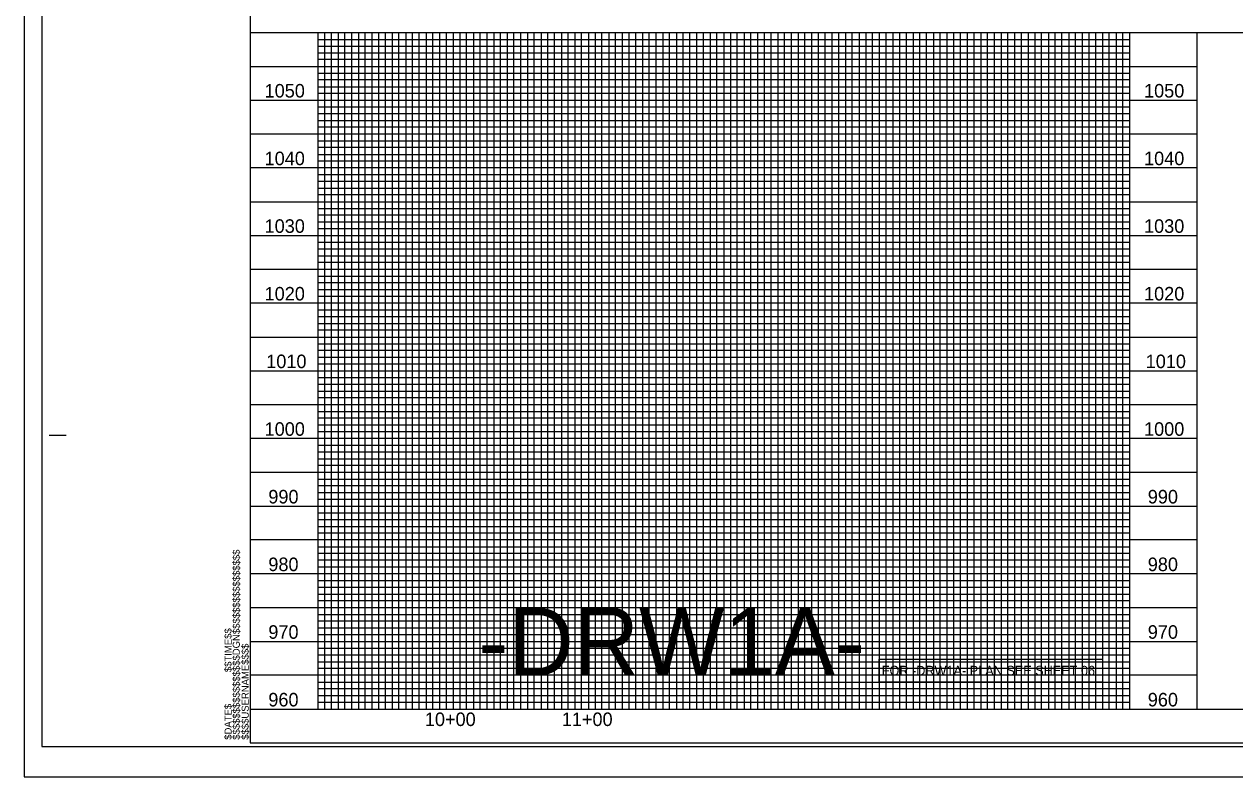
# Model space of a CAD drawing. Extents: x 1260439 to 1262228, y 742196 to 743296.
# Drawn here: x 1260439 to 1261333, y 742196 to 742752 of the extents above; entities that cross this region are included whole.
import ezdxf

# ---------------------------------------------------------------- set-up
doc = ezdxf.new("R2010")
doc.units = 0
for name, color, linetype in [('Exist Vertical Profile Horizontal Axis Label Major', 7, 'Continuous'), ('Exist Vertical Profile Vertical Axis Label', 7, 'Continuous'), ('Prop Grid Mask', 7, 'Continuous'), ('Prop PFL Text', 7, 'Continuous'), ('Sheet Block System Information CELL', 7, 'Continuous'), ('Sheet Cutting Line CELL', 7, 'Continuous'), ('Sheet Data Field CELL', 7, 'Continuous'), ('Sheet Plot Border Inside CELL', 7, 'Continuous'), ('Sheet Plot Border Outside CELL', 7, 'Continuous'), ('Sheet Profile CELL', 7, 'Continuous'), ('Sheet Profile Grid Major CELL', 7, 'Continuous'), ('Sheet Profile Grid Middle CELL', 7, 'Continuous'), ('Sheet Profile Grid Minor CELL', 7, 'Continuous')]:
    doc.layers.add(name, color=color, linetype=linetype)

msp = doc.modelspace()

# ---------------------------------------------------------------- linework, layer by layer
at = {"layer": 'Prop Grid Mask'}
msp.add_lwpolyline([(1261070.75, 742282.74), (1261235.75, 742282.74), (1261235.75, 742265.74), (1261070.75, 742265.74)], close=True, dxfattribs=at)
at = {"layer": 'Sheet Block System Information CELL'}
msp.add_line((1260605.75, 742220.74), (1260605.75, 742220.74), dxfattribs=at)
at = {"layer": 'Sheet Cutting Line CELL'}
msp.add_line((1260438.75, 743295.74), (1260438.75, 742195.74), dxfattribs=at)
at = {"layer": 'Sheet Plot Border Inside CELL'}
msp.add_lwpolyline([(1260451.75, 742218.19), (1262118.25, 742218.19), (1262118.25, 743273.29), (1260451.75, 743273.29)], close=True, dxfattribs=at)
at = {"layer": 'Sheet Plot Border Outside CELL'}
msp.add_lwpolyline([(1260438.75, 742195.74), (1262122.75, 742195.74), (1262122.75, 743295.74), (1260438.75, 743295.74)], close=True, dxfattribs=at)
at = {"layer": 'Sheet Profile CELL'}
for p, q in [((1260605.75, 742745.74), (1262105.75, 742745.74)), ((1260457.25, 742448.24), (1260469.75, 742448.24)), ((1260605.75, 742245.74), (1262105.75, 742245.74))]:
    msp.add_line(p, q, dxfattribs=at)
msp.add_lwpolyline([(1262105.75, 743270.74), (1260605.75, 743270.74), (1260605.75, 742220.74), (1262105.75, 742220.74)], close=True, dxfattribs=at)
at = {"layer": 'Sheet Profile Grid Major CELL'}
for p, q in [((1260655.75, 742745.74), (1260655.75, 742245.74)), ((1260705.75, 742245.74), (1260705.75, 742745.74)), ((1260705.75, 742745.74), (1260755.75, 742745.74)), ((1260755.75, 742745.74), (1260755.75, 742245.74)), ((1260805.75, 742245.74), (1260805.75, 742745.74)), ((1260805.75, 742745.74), (1260855.75, 742745.74)), ((1260855.75, 742745.74), (1260855.75, 742245.74)), ((1260905.75, 742245.74), (1260905.75, 742745.74)), ((1260905.75, 742745.74), (1260955.75, 742745.74)), ((1260955.75, 742745.74), (1260955.75, 742245.74)), ((1261005.75, 742245.74), (1261005.75, 742745.74)), ((1261005.75, 742745.74), (1261055.75, 742745.74)), ((1261055.75, 742745.74), (1261055.75, 742245.74)), ((1261105.75, 742745.74), (1261155.75, 742745.74)), ((1261105.75, 742245.74), (1261105.75, 742745.74)), ((1261105.75, 742745.74), (1261155.75, 742745.74)), ((1261155.75, 742745.74), (1261155.75, 742245.74)), ((1261205.75, 742745.74), (1261255.75, 742745.74)), ((1261205.75, 742245.74), (1261205.75, 742745.74)), ((1261255.75, 742745.74), (1261255.75, 742245.74)), ((1261305.75, 742745.74), (1261355.75, 742745.74)), ((1261305.75, 742245.74), (1261305.75, 742745.74)), ((1260605.75, 742245.74), (1260605.75, 742245.74)), ((1260655.75, 742245.74), (1260705.75, 742245.74)), ((1260755.75, 742245.74), (1260805.75, 742245.74)), ((1260855.75, 742245.74), (1260905.75, 742245.74)), ((1260955.75, 742245.74), (1261005.75, 742245.74)), ((1261055.75, 742245.74), (1261105.75, 742245.74)), ((1261155.75, 742245.74), (1261205.75, 742245.74)), ((1261255.75, 742245.74), (1261305.75, 742245.74))]:
    msp.add_line(p, q, dxfattribs=at)
for points in [[(1260605.75, 742695.74), (1261305.75, 742695.74)], [(1261305.75, 742645.74), (1260605.75, 742645.74), (1260605.75, 742595.74), (1261305.75, 742595.74)], [(1261305.75, 742545.74), (1260605.75, 742545.74), (1260605.75, 742495.74), (1261305.75, 742495.74)], [(1261305.75, 742445.74), (1260605.75, 742445.74), (1260605.75, 742395.74), (1261305.75, 742395.74)], [(1261305.75, 742345.74), (1260605.75, 742345.74), (1260605.75, 742345.74), (1260605.75, 742295.74), (1261305.75, 742295.74)]]:
    msp.add_lwpolyline(points, dxfattribs=at)
at = {"layer": 'Sheet Profile Grid Middle CELL'}
for p, q in [((1260680.75, 742745.74), (1260680.75, 742245.74)), ((1260730.75, 742245.74), (1260730.75, 742745.74)), ((1260730.75, 742745.74), (1260780.75, 742745.74)), ((1260780.75, 742745.74), (1260780.75, 742245.74)), ((1260830.75, 742245.74), (1260830.75, 742745.74)), ((1260830.75, 742745.74), (1260880.75, 742745.74)), ((1260880.75, 742745.74), (1260880.75, 742245.74)), ((1260930.75, 742245.74), (1260930.75, 742745.74)), ((1260930.75, 742745.74), (1260980.75, 742745.74)), ((1260980.75, 742745.74), (1260980.75, 742245.74)), ((1261030.75, 742245.74), (1261030.75, 742745.74)), ((1261030.75, 742745.74), (1261080.75, 742745.74)), ((1261080.75, 742745.74), (1261080.75, 742245.74)), ((1261130.75, 742245.74), (1261130.75, 742745.74)), ((1261180.75, 742745.74), (1261180.75, 742245.74)), ((1261230.75, 742245.74), (1261230.75, 742745.74)), ((1260605.75, 742720.74), (1261305.75, 742720.74)), ((1260680.75, 742245.74), (1260730.75, 742245.74)), ((1260780.75, 742245.74), (1260830.75, 742245.74)), ((1260880.75, 742245.74), (1260930.75, 742245.74)), ((1260980.75, 742245.74), (1261030.75, 742245.74)), ((1261080.75, 742245.74), (1261130.75, 742245.74)), ((1261230.75, 742245.74), (1261230.75, 742245.74))]:
    msp.add_line(p, q, dxfattribs=at)
for points in [[(1261305.75, 742670.74), (1260605.75, 742670.74), (1260605.75, 742620.74), (1261305.75, 742620.74)], [(1261305.75, 742570.74), (1260605.75, 742570.74), (1260605.75, 742520.74), (1261305.75, 742520.74)], [(1261305.75, 742470.74), (1260605.75, 742470.74), (1260605.75, 742420.74), (1261305.75, 742420.74)], [(1261305.75, 742370.74), (1260605.75, 742370.74), (1260605.75, 742320.74), (1261305.75, 742320.74)], [(1261305.75, 742270.74), (1260605.75, 742270.74)]]:
    msp.add_lwpolyline(points, dxfattribs=at)
at = {"layer": 'Sheet Profile Grid Minor CELL'}
for p, q in [((1260655.75, 742740.74), (1261255.75, 742740.74)), ((1260655.75, 742735.74), (1260655.75, 742735.74)), ((1261255.75, 742735.56), (1260655.75, 742735.39)), ((1260655.75, 742730.74), (1261255.75, 742730.74)), ((1261255.75, 742610.74), (1260655.75, 742610.74)), ((1261255.75, 742605.74), (1260655.75, 742605.74)), ((1261255.75, 742600.74), (1260655.75, 742600.74)), ((1260655.75, 742590.74), (1261255.75, 742590.74)), ((1261255.75, 742585.74), (1260655.75, 742585.74)), ((1260655.75, 742580.74), (1261255.75, 742580.74)), ((1261255.75, 742560.74), (1260655.75, 742560.74)), ((1260655.75, 742555.74), (1261255.75, 742555.74)), ((1261255.75, 742535.74), (1260655.75, 742535.74)), ((1260655.75, 742530.74), (1261255.75, 742530.74)), ((1261255.75, 742510.74), (1260655.75, 742510.74)), ((1260655.75, 742505.74), (1261255.75, 742505.74)), ((1261255.75, 742500.74), (1260655.75, 742500.74)), ((1260655.75, 742490.74), (1261255.75, 742490.74)), ((1261255.75, 742485.74), (1260655.75, 742485.74)), ((1260655.75, 742480.74), (1261255.75, 742480.74)), ((1261255.75, 742475.74), (1260655.75, 742475.74)), ((1260655.75, 742465.74), (1261255.75, 742465.74)), ((1261255.75, 742460.74), (1260655.75, 742460.74)), ((1260655.75, 742455.74), (1261255.75, 742455.74)), ((1261255.75, 742450.74), (1260655.75, 742450.74)), ((1260655.75, 742440.74), (1261255.75, 742440.74)), ((1261255.75, 742435.74), (1260655.75, 742435.74)), ((1260655.75, 742430.74), (1261255.75, 742430.74)), ((1261255.75, 742425.74), (1260655.75, 742425.74)), ((1260655.75, 742415.74), (1261255.75, 742415.74)), ((1261255.75, 742410.74), (1260655.75, 742410.74)), ((1260655.75, 742405.74), (1261255.75, 742405.74)), ((1261255.75, 742400.74), (1260655.75, 742400.74)), ((1260655.75, 742390.74), (1261255.75, 742390.74)), ((1261255.75, 742385.74), (1260655.75, 742385.74)), ((1260655.75, 742380.74), (1261255.75, 742380.74)), ((1261255.75, 742375.74), (1260655.75, 742375.74)), ((1260655.75, 742365.74), (1261255.75, 742365.74)), ((1261255.75, 742360.74), (1260655.75, 742360.74)), ((1261255.75, 742355.74), (1260655.75, 742355.74)), ((1261255.75, 742350.74), (1260655.75, 742350.74)), ((1260655.75, 742340.74), (1261255.75, 742340.74)), ((1261255.75, 742335.74), (1260655.75, 742335.74)), ((1260655.75, 742330.74), (1261255.75, 742330.74)), ((1261255.75, 742325.74), (1260655.75, 742325.74)), ((1260655.75, 742315.74), (1261255.75, 742315.74)), ((1261255.75, 742310.74), (1260655.75, 742310.74)), ((1260655.75, 742305.74), (1261255.75, 742305.74)), ((1261255.75, 742300.74), (1260655.75, 742300.74)), ((1260655.75, 742290.74), (1261255.75, 742290.74)), ((1261255.75, 742285.74), (1260655.75, 742285.74)), ((1260655.75, 742280.74), (1261255.75, 742280.74)), ((1261255.75, 742275.74), (1260655.75, 742275.74)), ((1260655.75, 742265.74), (1261255.75, 742265.74)), ((1261255.75, 742260.74), (1260655.75, 742260.74)), ((1260655.75, 742255.74), (1261255.75, 742255.74))]:
    msp.add_line(p, q, dxfattribs=at)
for points in [[(1260660.75, 742745.74), (1260660.75, 742245.74), (1260665.75, 742245.74), (1260665.75, 742745.74), (1260670.75, 742745.74), (1260670.75, 742245.74), (1260675.75, 742245.74), (1260675.75, 742745.74), (1260685.75, 742745.74), (1260685.75, 742245.74), (1260690.75, 742245.74), (1260690.75, 742745.74), (1260695.75, 742745.74), (1260695.75, 742245.74), (1260700.75, 742245.74), (1260710.75, 742245.74), (1260715.75, 742245.74), (1260715.75, 742745.74), (1260720.75, 742745.74), (1260720.75, 742245.74), (1260725.75, 742245.74), (1260725.75, 742745.74), (1260735.75, 742745.74), (1260735.75, 742245.74), (1260740.75, 742245.74), (1260740.75, 742745.74), (1260745.75, 742745.74), (1260745.75, 742245.74), (1260750.75, 742245.74), (1260750.75, 742745.74), (1260760.75, 742745.74), (1260760.75, 742245.74), (1260765.75, 742245.74), (1260765.75, 742745.74), (1260770.75, 742745.74), (1260770.75, 742245.74), (1260775.75, 742245.74), (1260775.75, 742745.74), (1260785.75, 742745.74), (1260785.75, 742245.74), (1260790.75, 742245.74), (1260790.75, 742745.74), (1260795.75, 742745.74), (1260795.75, 742245.74), (1260800.75, 742245.74), (1260800.75, 742745.74), (1260810.75, 742745.74), (1260810.75, 742245.74), (1260815.75, 742245.74), (1260815.75, 742745.74), (1260820.75, 742745.74), (1260820.75, 742245.74), (1260825.75, 742245.74), (1260825.75, 742745.74), (1260835.75, 742745.74), (1260835.75, 742245.74), (1260840.75, 742245.74), (1260840.75, 742745.74), (1260845.75, 742745.74), (1260845.75, 742245.74), (1260850.75, 742245.74), (1260850.75, 742745.74), (1260860.75, 742745.74), (1260860.75, 742245.74), (1260865.75, 742245.74), (1260865.75, 742745.74), (1260870.75, 742745.74), (1260870.75, 742245.74)], [(1260700.75, 742245.74), (1260700.75, 742745.74), (1260710.75, 742745.74), (1260710.75, 742245.74)], [(1260870.75, 742245.74), (1260875.75, 742245.74), (1260875.75, 742745.74), (1260885.75, 742745.74), (1260885.75, 742245.74), (1260890.75, 742245.74), (1260890.75, 742745.74), (1260895.75, 742745.74), (1260895.75, 742245.74), (1260900.75, 742245.74), (1260900.75, 742745.74), (1260910.75, 742745.74), (1260910.75, 742245.74), (1260915.75, 742245.74), (1260915.75, 742745.74), (1260920.75, 742745.74), (1260920.75, 742245.74), (1260925.75, 742245.74), (1260925.75, 742745.74), (1260935.75, 742745.74), (1260935.75, 742245.74), (1260940.75, 742245.74), (1260940.75, 742745.74), (1260945.75, 742745.74), (1260945.75, 742245.74), (1260950.75, 742245.74), (1260950.75, 742745.74), (1260960.75, 742745.74), (1260960.75, 742245.74), (1260965.75, 742245.74), (1260965.75, 742745.74), (1260970.75, 742745.74), (1260970.75, 742245.74), (1260975.75, 742245.74), (1260975.75, 742745.74), (1260985.75, 742745.74), (1260985.75, 742245.74), (1260990.75, 742245.74), (1260990.75, 742745.74), (1260995.75, 742745.74), (1260995.75, 742245.74), (1261000.75, 742245.74), (1261000.75, 742745.74), (1261010.75, 742745.74), (1261010.75, 742245.74), (1261015.75, 742245.74), (1261015.75, 742745.74), (1261020.75, 742745.74), (1261020.75, 742245.74), (1261025.75, 742245.74), (1261025.75, 742745.74), (1261035.75, 742745.74), (1261035.75, 742245.74), (1261040.75, 742245.74), (1261040.75, 742745.74), (1261045.75, 742745.74), (1261045.75, 742245.74), (1261050.75, 742245.74), (1261050.75, 742745.74), (1261060.75, 742745.74), (1261060.75, 742245.74), (1261065.75, 742245.74), (1261065.75, 742745.74), (1261070.75, 742745.74), (1261070.75, 742245.74), (1261075.75, 742245.74), (1261075.75, 742745.74), (1261085.75, 742745.74), (1261085.75, 742245.74), (1261090.75, 742245.74), (1261090.75, 742745.74), (1261095.75, 742745.74), (1261095.75, 742245.74), (1261100.75, 742245.74), (1261100.75, 742745.74), (1261110.75, 742745.74), (1261110.75, 742245.74), (1261115.75, 742245.74), (1261115.75, 742745.74), (1261120.75, 742745.74), (1261120.75, 742245.74), (1261125.75, 742245.74), (1261125.75, 742745.74), (1261135.75, 742745.74), (1261135.75, 742245.74), (1261140.75, 742245.74), (1261140.75, 742745.74), (1261145.75, 742745.74), (1261145.75, 742245.74), (1261150.75, 742245.74), (1261150.75, 742745.74), (1261255.75, 742745.74)], [(1261145.75, 742245.74), (1261150.75, 742245.74), (1261150.75, 742745.74), (1261160.75, 742745.74), (1261160.75, 742245.74), (1261165.75, 742245.74), (1261165.75, 742745.74), (1261170.75, 742745.74), (1261170.75, 742245.74), (1261175.75, 742245.74), (1261175.75, 742745.74), (1261185.75, 742745.74), (1261185.75, 742245.74), (1261190.75, 742245.74), (1261190.75, 742745.74), (1261195.75, 742745.74), (1261195.75, 742245.74), (1261200.75, 742245.74), (1261200.75, 742745.74), (1261210.75, 742745.74), (1261210.75, 742245.74), (1261215.75, 742245.74), (1261215.75, 742745.74), (1261220.75, 742745.74), (1261220.75, 742245.74), (1261225.75, 742245.74), (1261225.75, 742745.74), (1261235.75, 742745.74), (1261235.75, 742245.74), (1261240.75, 742245.74), (1261240.75, 742745.74), (1261245.75, 742745.74), (1261245.75, 742245.74), (1261250.75, 742245.74), (1261250.75, 742745.74), (1261255.75, 742745.74)], [(1261255.75, 742725.74), (1260655.75, 742725.74), (1260655.75, 742715.74), (1261255.75, 742715.74)], [(1261255.75, 742710.74), (1260655.75, 742710.74), (1260655.75, 742705.74), (1261255.75, 742705.74)], [(1261255.75, 742700.74), (1260655.75, 742700.74), (1260655.75, 742690.74), (1261255.75, 742690.74)], [(1261255.75, 742685.74), (1260655.75, 742685.74), (1260655.75, 742680.74), (1261255.75, 742680.74)], [(1261255.75, 742675.74), (1260655.75, 742675.74), (1260655.75, 742665.74), (1261255.75, 742665.74)], [(1261255.75, 742660.74), (1260655.75, 742660.74), (1260655.75, 742655.74), (1261255.75, 742655.74)], [(1261255.75, 742650.74), (1260655.75, 742650.74), (1260655.75, 742640.74), (1261255.75, 742640.74)], [(1261255.75, 742635.64), (1260655.85, 742635.64), (1260655.85, 742630.74), (1261255.75, 742630.74)], [(1261255.75, 742625.74), (1260655.75, 742625.74), (1260655.75, 742615.74), (1261255.75, 742615.74)], [(1261255.75, 742575.74), (1260655.75, 742575.74), (1260655.75, 742565.74), (1261255.75, 742565.74)], [(1261255.75, 742550.74), (1260655.75, 742550.74), (1260655.75, 742540.74), (1261255.75, 742540.74)], [(1261255.75, 742525.74), (1260655.75, 742525.74), (1260655.75, 742515.74), (1261255.75, 742515.74)], [(1261255.75, 742250.74), (1260655.75, 742250.74)]]:
    msp.add_lwpolyline(points, dxfattribs=at)

# ---------------------------------------------------------------- texts
at = {"layer": 'Exist Vertical Profile Horizontal Axis Label Major'}
for s, p in [('10+00', (1260734.88, 742233.24)), ('10+00', (1260734.88, 742233.24)), ('11+00', (1260836.08, 742233.24)), ('11+00', (1260836.08, 742233.24))]:
    msp.add_text(s, height=10, dxfattribs=at).set_placement(p)
at = {"layer": 'Exist Vertical Profile Vertical Axis Label'}
for s, p in [('1050', (1260616.43, 742697.74)), ('1050', (1261266.43, 742697.74)), ('1040', (1260616.43, 742647.74)), ('1040', (1261266.43, 742647.74)), ('1030', (1260616.43, 742597.74)), ('1030', (1261266.43, 742597.74)), ('1020', (1260616.43, 742547.74)), ('1020', (1261266.43, 742547.74)), ('1010', (1260617.63, 742497.74)), ('1010', (1261267.63, 742497.74)), ('1000', (1260616.43, 742447.74)), ('1000', (1261266.43, 742447.74)), ('990', (1260619.19, 742397.74)), ('990', (1261269.19, 742397.74)), ('980', (1260619.19, 742347.74)), ('980', (1261269.19, 742347.74)), ('970', (1260619.19, 742297.74)), ('970', (1261269.19, 742297.74)), ('960', (1260619.19, 742247.74)), ('960', (1261269.19, 742247.74))]:
    msp.add_text(s, height=10, dxfattribs=at).set_placement(p)
at = {"layer": 'Prop PFL Text'}
msp.add_text('FOR -DRW1A- PLAN SEE SHEET 06', height=7, dxfattribs=at).set_placement((1261072.59, 742270.74))
at = {"layer": 'Sheet Block System Information CELL'}
for s, p in [('$$$$$$$$$$$$$$$$DGN$$$$$$$$$$$$$$$$', (1260598.1, 742223.1)), ('$$TIME$$', (1260592.05, 742273.1)), ('$$$$USERNAME$$$$', (1260604.68, 742223.11)), ('$DATE$', (1260592.05, 742223.1))]:
    msp.add_text(s, height=5.25, rotation=90, dxfattribs=at).set_placement(p)
at = {"layer": 'Sheet Data Field CELL'}
msp.add_text('-DRW1A-', height=50, dxfattribs=at).set_placement((1260774.31, 742270.74))

doc.saveas('drawing.dxf')
